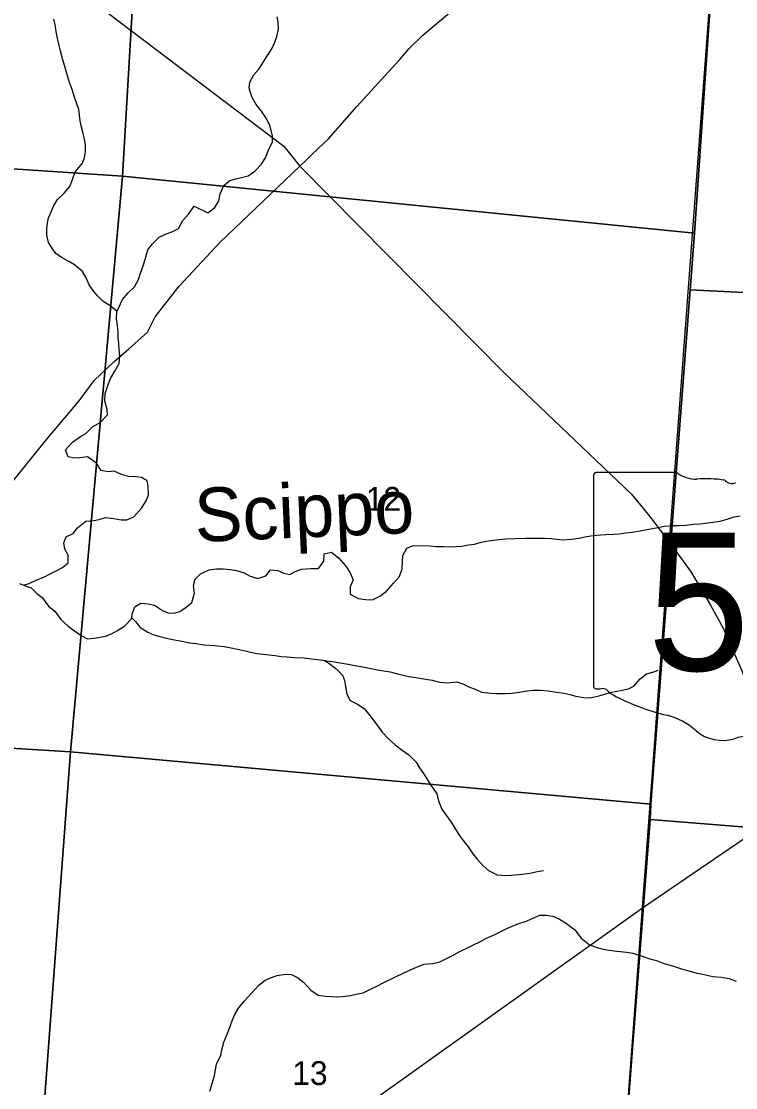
# Model space of a CAD drawing. Extents: x 0 to 42.5, y 0 to 22.
# Drawn here: x 4.816 to 5.445, y 17.595 to 18.534 of the extents above; entities that cross this region are included whole.
import ezdxf

# ---------------------------------------------------------------- set-up
doc = ezdxf.new("R2010")
doc.units = 0
for name, color, linetype in [('GM_X_Interchange_Ramps', 7, 'Continuous'), ('GM_X_Minor_River', 7, 'Continuous'), ('GM_X_Minor_River_Text', 7, 'Continuous'), ('GM_X_Section', 7, 'Continuous'), ('GM_X_Section_Text', 7, 'Continuous'), ('GM_X_State_Location', 7, 'Continuous'), ('GM_X_State_Route', 7, 'Continuous'), ('GM_X_State_Shield', 7, 'Continuous'), ('GM_X_Township', 7, 'Continuous'), ('GM_X_Township_Road', 7, 'Continuous')]:
    doc.layers.add(name, color=color, linetype=linetype)

msp = doc.modelspace()

# ---------------------------------------------------------------- linework, layer by layer
at = {"layer": 'GM_X_Interchange_Ramps'}
msp.add_lwpolyline([(5.32269, 17.21064), (5.36305, 17.75335), (5.38697, 18.0749), (5.4438, 18.83893), (5.43521, 18.83912), (4.92631, 18.87711), (4.75971, 18.88954), (4.67232, 18.89662), (4.3409, 18.92195), (4.15813, 18.93579), (4.14675, 18.93523), (3.92131, 18.95204), (3.91408, 18.95319), (3.69662, 18.96404), (3.63582, 18.96841), (3.50971, 18.97621), (3.49687, 18.97472), (3.39197, 18.98393), (3.37742, 18.98467), (3.37078, 18.98615), (3.11995, 19.00104)], dxfattribs=at)
at = {"layer": 'GM_X_Minor_River'}
for points in [[(4.90024, 18.27843), (4.89402, 18.28337), (4.88772, 18.2876), (4.88295, 18.29219), (4.87914, 18.29697), (4.87551, 18.30193), (4.87304, 18.30803), (4.8698, 18.31375), (4.86274, 18.3195), (4.85758, 18.32258), (4.85108, 18.32624), (4.84612, 18.3295), (4.84307, 18.33427), (4.83983, 18.33923), (4.83831, 18.3457), (4.83832, 18.3514), (4.83891, 18.35615), (4.83987, 18.36089), (4.84237, 18.36676), (4.84449, 18.37187), (4.84775, 18.37698), (4.85369, 18.38282), (4.85849, 18.38848), (4.86118, 18.39549), (4.8633, 18.40137), (4.86981, 18.40911), (4.87155, 18.41422), (4.87251, 18.41934), (4.87234, 18.42505), (4.87139, 18.43056), (4.87025, 18.43532), (4.86893, 18.44083), (4.86779, 18.44654), (4.86723, 18.4513), (4.86647, 18.45643), (4.86267, 18.46728), (4.86077, 18.47395), (4.85811, 18.48099), (4.85659, 18.48594), (4.85431, 18.49413), (4.85203, 18.50098), (4.85033, 18.50783), (4.84881, 18.5143), (4.84767, 18.51906), (4.84654, 18.52515), (4.84559, 18.53085), (4.84446, 18.53599)], [(4.96804, 18.37116), (4.98027, 18.36537), (4.9864, 18.37008), (4.98986, 18.37594), (4.99102, 18.38201), (4.99428, 18.3894), (4.99965, 18.39392), (5.00482, 18.3954), (5.01094, 18.39668), (5.01572, 18.39798), (5.02147, 18.40193), (5.02703, 18.40796), (5.03087, 18.41382), (5.03356, 18.42064), (5.03702, 18.42803), (5.03703, 18.43316), (5.03589, 18.43791), (5.03437, 18.44305), (5.03094, 18.44954), (5.02751, 18.45507), (5.02275, 18.4608), (5.01893, 18.46748), (5.01646, 18.47528), (5.01705, 18.48041), (5.0207, 18.48703), (5.02549, 18.49231), (5.02856, 18.49742), (5.03221, 18.50309), (5.03643, 18.5099), (5.03931, 18.51558), (5.04104, 18.52069), (5.0424, 18.52714), (5.04222, 18.53322), (5.04127, 18.53798)], [(4.8179, 18.03728), (4.82273, 18.03886), (4.82943, 18.04204), (4.83555, 18.04447), (4.8413, 18.04727), (4.84723, 18.05027), (4.85202, 18.05289), (4.857, 18.05704), (4.85702, 18.06368), (4.85416, 18.06921), (4.85322, 18.07454), (4.85533, 18.07984), (4.86146, 18.08303), (4.8653, 18.08794), (4.87258, 18.09377), (4.88023, 18.09429), (4.8852, 18.09539), (4.88999, 18.09687), (4.89745, 18.09625), (4.90375, 18.09507), (4.90873, 18.09484), (4.91504, 18.09745), (4.92214, 18.10538), (4.92617, 18.11238), (4.9279, 18.11711), (4.92753, 18.12452), (4.92678, 18.12928), (4.92162, 18.13216), (4.91608, 18.13278), (4.91015, 18.13301), (4.90422, 18.13476), (4.89754, 18.13785), (4.89237, 18.13732), (4.88625, 18.13831), (4.88206, 18.14499), (4.87404, 18.15037), (4.86753, 18.14946), (4.86256, 18.14931), (4.85702, 18.15049), (4.85473, 18.15658), (4.86087, 18.16338), (4.86796, 18.16827), (4.87274, 18.17089), (4.87888, 18.1773), (4.885, 18.1803), (4.89171, 18.18747), (4.89134, 18.19222), (4.88944, 18.19964), (4.88965, 18.20629), (4.89196, 18.2133), (4.89427, 18.21955), (4.89811, 18.22598), (4.90195, 18.2326), (4.90273, 18.23924), (4.90217, 18.24476), (4.9018, 18.25027), (4.90123, 18.2554), (4.90124, 18.26015), (4.90068, 18.26623), (4.89974, 18.27213), (4.90013, 18.2782), (4.90513, 18.28899), (4.90993, 18.29485), (4.91548, 18.30012), (4.91913, 18.30656), (4.92086, 18.31224), (4.92356, 18.31944), (4.92548, 18.32645), (4.92741, 18.33271), (4.93144, 18.338), (4.93738, 18.34384), (4.94446, 18.34721), (4.94944, 18.34907), (4.95423, 18.35151), (4.95826, 18.35851), (4.96325, 18.36417), (4.96804, 18.37116)], [(5.10829, 18.0421), (5.10541, 18.03605), (5.10559, 18.02959), (5.11266, 18.02555), (5.11935, 18.02474), (5.12528, 18.0245), (5.13179, 18.02769), (5.13753, 18.0322), (5.14367, 18.03919), (5.14904, 18.04504), (5.15135, 18.05167), (5.15155, 18.05755), (5.15195, 18.06363), (5.1556, 18.07006), (5.16057, 18.07192), (5.16746, 18.07244), (5.17606, 18.072), (5.18104, 18.07159), (5.18792, 18.07135), (5.19404, 18.07111), (5.19902, 18.07146), (5.2038, 18.0718), (5.20992, 18.0729), (5.21509, 18.07362), (5.22102, 18.07528), (5.22752, 18.07657), (5.23422, 18.07747), (5.24226, 18.07817), (5.25105, 18.07848), (5.26043, 18.0788), (5.27688, 18.07868), (5.2828, 18.07844), (5.28758, 18.07803), (5.29275, 18.07742), (5.30059, 18.07794), (5.30729, 18.07884), (5.31379, 18.08012), (5.31953, 18.08103), (5.32623, 18.08174), (5.3312, 18.08189), (5.3377, 18.08222), (5.34268, 18.08257), (5.3488, 18.08347), (5.35416, 18.08419), (5.36105, 18.08528), (5.3687, 18.08675), (5.37654, 18.08821), (5.38248, 18.0895), (5.39032, 18.09001), (5.39548, 18.08997), (5.40103, 18.09031), (5.40792, 18.09102), (5.41347, 18.09155), (5.41863, 18.09208), (5.42514, 18.09299), (5.43145, 18.09389), (5.43757, 18.09556), (5.4437, 18.0976), (5.44906, 18.09851)], [(4.81431, 18.03873), (4.81909, 18.0368), (4.82444, 18.03505), (4.8294, 18.03007), (4.83418, 18.02662), (4.83971, 18.01879), (4.84525, 18.01457), (4.85078, 18.00713), (4.85688, 18.00157), (4.8628, 17.99716), (4.86853, 17.99294), (4.87407, 17.99005), (4.88192, 17.99094), (4.89014, 17.99259), (4.89531, 17.99465), (4.90048, 17.99746), (4.907, 18.00159), (4.91294, 18.00781), (4.91391, 18.01275), (4.91583, 18.01843), (4.92119, 18.02143), (4.9275, 18.02081), (4.93324, 18.01982), (4.94011, 18.01502), (4.94489, 18.0129), (4.95063, 18.01267), (4.9556, 18.01415), (4.96097, 18.01791), (4.96614, 18.02205), (4.96845, 18.03039), (4.96751, 18.03705), (4.96886, 18.04274), (4.97365, 18.04726), (4.98131, 18.05081), (4.98782, 18.05191), (4.99356, 18.05186), (4.99967, 18.05106), (5.00541, 18.05026), (5.0121, 18.04831), (5.01745, 18.04523), (5.02433, 18.04328), (5.03122, 18.04551), (5.03544, 18.05099), (5.04194, 18.05018), (5.0471, 18.04787), (5.05226, 18.04669), (5.05724, 18.04931), (5.06279, 18.05136), (5.07083, 18.05206), (5.07752, 18.05201), (5.08232, 18.05863), (5.08252, 18.06508), (5.08922, 18.06655), (5.09571, 18.06119), (5.10162, 18.05412), (5.10563, 18.0482), (5.10829, 18.0421)], [(4.91312, 18.00874), (4.91676, 18.00513), (4.92038, 18.00035), (4.92726, 17.99612), (4.93261, 17.99361), (4.93796, 17.99206), (4.94503, 17.99048), (4.95077, 17.9893), (4.95727, 17.98812), (4.96434, 17.98674), (4.9695, 17.98613), (4.97696, 17.98474), (4.98595, 17.98411), (4.99455, 17.98348), (5.00086, 17.98229), (5.01195, 17.97974), (5.01769, 17.97837), (5.02361, 17.97719), (5.03145, 17.97618), (5.03948, 17.97536), (5.04465, 17.97456), (5.05, 17.97415), (5.05689, 17.97372), (5.06492, 17.97328), (5.07161, 17.97247), (5.07907, 17.97166), (5.085, 17.97085), (5.09188, 17.96985), (5.09666, 17.96906), (5.10373, 17.96787), (5.10966, 17.96668), (5.11501, 17.96569), (5.12094, 17.96451), (5.12954, 17.96293), (5.13509, 17.96194), (5.14082, 17.96095), (5.14828, 17.959), (5.15726, 17.95703), (5.16338, 17.95604), (5.17218, 17.95445), (5.17772, 17.95365), (5.18441, 17.95208), (5.19168, 17.95146), (5.19952, 17.95235), (5.20487, 17.95042), (5.21003, 17.94791), (5.21634, 17.94539), (5.22131, 17.94327), (5.22915, 17.94226), (5.23393, 17.94185), (5.24215, 17.94198), (5.24827, 17.94231), (5.25478, 17.94322), (5.25956, 17.94394), (5.26664, 17.94484), (5.27314, 17.94479), (5.28003, 17.94417), (5.28538, 17.94337), (5.29379, 17.94217), (5.29915, 17.94099), (5.3045, 17.93963), (5.31119, 17.93844), (5.31616, 17.93821), (5.32114, 17.93893), (5.32592, 17.94023), (5.33358, 17.94264), (5.33913, 17.94374), (5.34525, 17.94503), (5.35061, 17.94594), (5.35539, 17.94856), (5.36095, 17.95479), (5.3667, 17.95931), (5.37206, 17.96079), (5.37685, 17.96265)], [(5.08208, 17.97125), (5.0869, 17.96875), (5.09282, 17.96396), (5.09874, 17.95822), (5.10064, 17.95345), (5.10139, 17.94813), (5.10253, 17.94128), (5.10558, 17.93594), (5.11188, 17.93248), (5.11799, 17.92863), (5.12276, 17.92271), (5.12944, 17.91412), (5.13382, 17.90782), (5.13897, 17.90227), (5.14527, 17.89671), (5.15138, 17.89192), (5.15711, 17.88808), (5.16379, 17.88139), (5.16665, 17.87662), (5.17027, 17.87146), (5.17656, 17.86116), (5.1819, 17.85371), (5.18342, 17.84743), (5.18627, 17.84019), (5.19085, 17.83389), (5.19447, 17.82855), (5.1979, 17.8232), (5.20172, 17.81729), (5.20515, 17.81251), (5.20953, 17.80678), (5.21373, 17.80086), (5.21754, 17.79609), (5.22231, 17.79055), (5.22728, 17.78595), (5.23492, 17.78229), (5.24257, 17.78166), (5.24773, 17.782), (5.25711, 17.78288), (5.2638, 17.78378), (5.27069, 17.78507), (5.27586, 17.78598)], [(5.1456, 17.69233), (5.15115, 17.69495), (5.15651, 17.69776), (5.16244, 17.70038), (5.17068, 17.70355), (5.17794, 17.70406), (5.18445, 17.70553), (5.18981, 17.70835), (5.1969, 17.71171), (5.20168, 17.71453), (5.20953, 17.71827), (5.21432, 17.7207), (5.21987, 17.72313), (5.22504, 17.72613), (5.23232, 17.72931), (5.23768, 17.73212), (5.24362, 17.73493), (5.24974, 17.73773), (5.25491, 17.73978), (5.26084, 17.74145), (5.26582, 17.74369), (5.27252, 17.74668), (5.27807, 17.74683), (5.28419, 17.74584), (5.29011, 17.74333), (5.29603, 17.73948), (5.30348, 17.73373), (5.3092, 17.72647), (5.31626, 17.72053), (5.32391, 17.71782), (5.32869, 17.71664), (5.33366, 17.71585), (5.34035, 17.71504), (5.34896, 17.71403), (5.3545, 17.71323), (5.36272, 17.7107), (5.3696, 17.70837), (5.37553, 17.7068), (5.38126, 17.70448), (5.39043, 17.70176), (5.39846, 17.69904), (5.40611, 17.69709), (5.41089, 17.69572), (5.41624, 17.69473), (5.42503, 17.69258), (5.43249, 17.69215), (5.43957, 17.69095), (5.44549, 17.68844)], [(4.98204, 17.59171), (4.98396, 17.59853), (4.98608, 17.60555), (4.98783, 17.6156), (4.99167, 17.62336), (4.99244, 17.6281), (4.99437, 17.63474), (4.99726, 17.64194), (4.99995, 17.64875), (5.00187, 17.65444), (5.00418, 17.65974), (5.00725, 17.66466), (5.01205, 17.67089), (5.01895, 17.67844), (5.02508, 17.68504), (5.03064, 17.68937), (5.03543, 17.69142), (5.04136, 17.69347), (5.04863, 17.69475), (5.05398, 17.69433), (5.05914, 17.69182), (5.06449, 17.68779), (5.07098, 17.68072), (5.07747, 17.6763), (5.08416, 17.6753), (5.09334, 17.67486), (5.0987, 17.67501), (5.10597, 17.6759), (5.11209, 17.67738), (5.11687, 17.67829), (5.12396, 17.68185), (5.12913, 17.68409), (5.13526, 17.68747), (5.14081, 17.69009), (5.1456, 17.69233)]]:
    msp.add_lwpolyline(points, dxfattribs=at)
at = {"layer": 'GM_X_Section'}
for points in [[(4.41142, 18.91319), (4.41842, 18.91278), (4.92537, 18.8751), (4.93294, 18.87432), (4.90498, 18.39769), (4.37823, 18.43283)], [(5.44269, 18.83716), (5.40881, 18.34747), (4.90498, 18.39769), (4.93294, 18.87432)], [(5.87382, 18.8051), (5.94404, 18.79959), (5.90839, 18.27246), (5.40504, 18.29767), (5.40881, 18.34747), (5.44269, 18.83716)], [(4.90498, 18.39769), (4.8591, 17.89062), (4.343, 17.92219), (4.37823, 18.43283)], [(5.40881, 18.34747), (5.40504, 18.29767), (5.37033, 17.84454), (4.8591, 17.89062), (4.90498, 18.39769)], [(5.90839, 18.27246), (5.86904, 17.79112), (5.36991, 17.83091), (5.37033, 17.84454), (5.40504, 18.29767)], [(4.343, 17.92219), (4.8591, 17.89062), (4.82097, 17.37842), (4.30758, 17.4121)], [(4.8591, 17.89062), (5.37033, 17.84454), (5.36991, 17.83091), (5.33145, 17.33215), (4.82097, 17.37842)], [(5.36991, 17.83091), (5.86904, 17.79112), (5.82691, 17.27078), (5.32925, 17.29977), (5.33145, 17.33215)]]:
    msp.add_lwpolyline(points, close=True, dxfattribs=at)
at = {"layer": 'GM_X_State_Route'}
for points in [[(4.34101, 18.92169), (4.59019, 18.77456), (4.62139, 18.75356), (4.65949, 18.71786), (4.7168, 18.67435), (5.04713, 18.42413), (5.06128, 18.40655), (5.24094, 18.22462), (5.31607, 18.15309)], [(5.36316, 17.75308), (5.49056, 17.83998), (5.89196, 18.10067), (6.10243, 18.24475), (6.12608, 18.25885), (6.17328, 18.28372), (6.39962, 18.34993), (6.70955, 18.44268), (6.75629, 18.44764), (6.83846, 18.45633), (6.85666, 18.45975), (6.8701, 18.46641), (6.90871, 18.49397), (6.91343, 18.49734)], [(5.31607, 18.15309), (5.35345, 18.1175), (5.36935, 18.0983), (5.38707, 18.07464), (5.40596, 18.0488), (5.42306, 18.0197), (5.43386, 18.0002), (5.45096, 17.96149), (5.45933, 17.93638)], [(3.7269, 15.97343), (4.12145, 16.58821), (4.14044, 16.61733), (4.30703, 16.86909), (4.39163, 16.96049), (4.54147, 17.12082), (4.6327, 17.22228), (4.64619, 17.23705), (5.03981, 17.52229), (5.36316, 17.75308)]]:
    msp.add_lwpolyline(points, dxfattribs=at)
at = {"layer": 'GM_X_State_Shield'}
for p, q in [((5.31984, 18.1335), (5.31984, 17.94916)), ((5.39336, 18.13667), (5.32223, 18.13667))]:
    msp.add_line(p, q, dxfattribs=at)
for centre, radius, start, end in [((5.32263, 18.13389), 0.00281, 98.1301, 188.1301), ((5.4103, 18.15807), 0.02729, 231.61951, 271.11188), ((5.41935, 18.03318), 0.09797, 80.48669, 94.98827), ((5.44159, 18.13484), 0.00787, 219.79206, 297.10237), ((5.32265, 17.94876), 0.00284, 171.95839, 258.30661), ((5.32308, 17.96762), 0.02166, 267.33899, 280.60386), ((5.32751, 17.93853), 0.00781, 29.74838, 93.27175), ((5.42613, 18.10414), 0.18599, 240.41292, 257.1985), ((5.37068, 17.86635), 0.05819, 47.18416, 75.83597), ((5.43362, 17.93761), 0.03693, 230.70037, 286.29184), ((5.45495, 17.87388), 0.03034, 85.69512, 111.20995)]:
    msp.add_arc(centre, radius, start, end, dxfattribs=at)
at = {"layer": 'GM_X_Township'}
msp.add_lwpolyline([(5.21422, 15.79865), (5.23885, 16.11392), (5.27199, 16.5652), (5.30219, 16.95892), (5.32269, 17.21064), (5.36305, 17.75335), (5.38697, 18.0749), (5.4438, 18.83893), (5.48124, 18.83572), (5.53918, 18.8313), (5.70411, 18.81873), (5.77651, 18.81321), (5.87419, 18.80629), (5.94448, 18.80075), (6.42536, 18.76104), (6.65154, 18.73968)], dxfattribs=at)
at = {"layer": 'GM_X_Township_Road'}
msp.add_line((5.3228, 17.21037), (5.36316, 17.75308), dxfattribs=at)
for points in [[(5.07213, 18.41695), (5.08645, 18.43068), (5.11152, 18.45904), (5.13925, 18.48948), (5.14919, 18.50045), (5.15742, 18.51009), (5.16965, 18.5218), (5.20229, 18.54916), (5.24524, 18.58634), (5.28246, 18.61747), (5.29946, 18.63315), (5.30709, 18.63918), (5.3174, 18.64843), (5.33258, 18.66451), (5.38912, 18.70333)], [(5.06128, 18.40655), (5.06675, 18.4118), (5.07213, 18.41695)], [(4.70668, 18.03545), (4.71753, 18.04365), (4.75082, 18.06968), (4.75962, 18.07585), (4.76863, 18.08449), (4.77993, 18.09423), (4.80783, 18.12812), (4.83843, 18.16597), (4.8669, 18.19984), (4.88001, 18.21755), (4.89727, 18.23408), (4.91029, 18.24514), (4.92697, 18.26034), (4.93377, 18.27375), (4.95495, 18.30087), (4.99086, 18.33923), (5.06128, 18.40655)]]:
    msp.add_lwpolyline(points, dxfattribs=at)

# ---------------------------------------------------------------- texts
at = {"layer": 'GM_X_Minor_River_Text'}
msp.add_text('Scippo', height=0.047347, rotation=2.45088, dxfattribs=at).set_placement((4.96934, 18.07533))
at = {"layer": 'GM_X_Section_Text'}
for s, p in [('12', (5.11932, 18.10293)), ('13', (5.05453, 17.59715))]:
    msp.add_text(s, height=0.020928, rotation=0.00001, dxfattribs=at).set_placement(p)
at = {"layer": 'GM_X_State_Location'}
msp.add_text('56', height=0.0000947, rotation=0.00001, dxfattribs=at).set_placement((5.42203, 17.97581))
at = {"layer": 'GM_X_State_Shield'}
msp.add_text('56', height=0.121435, dxfattribs=at).set_placement((5.3673, 17.96216))

doc.saveas('drawing.dxf')
